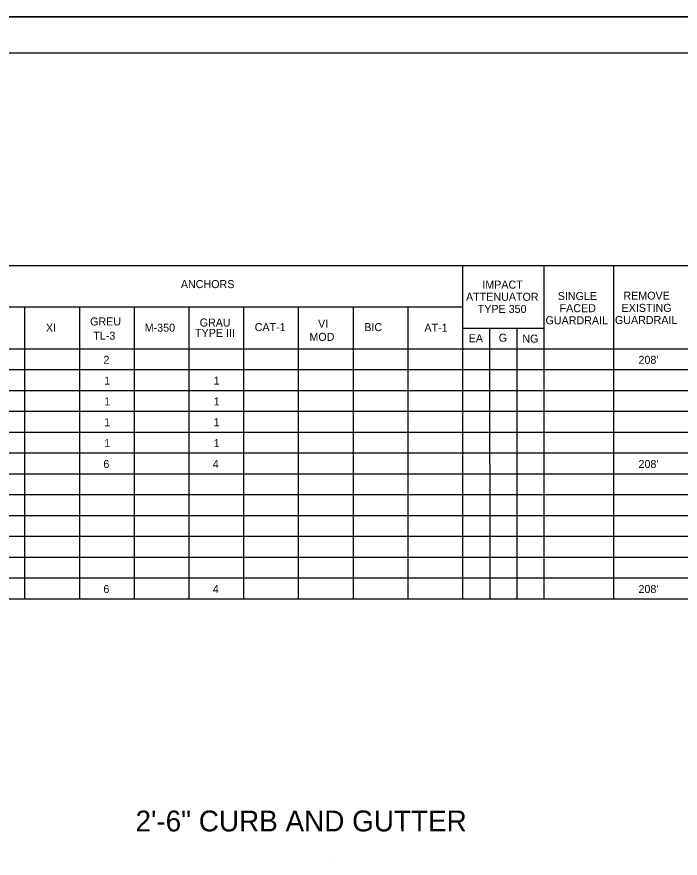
# Model space of a CAD drawing. Extents: x 1184121 to 1184360, y 1246506 to 1246661.
# Drawn here: x 1184248.8 to 1184306.6, y 1246587.1 to 1246660.5 of the extents above; entities that cross this region are included whole.
import ezdxf

# ---------------------------------------------------------------- set-up
doc = ezdxf.new("R2010")
doc.units = 0
for name, color, linetype in [('Sheet Data Field CELL', 7, 'Continuous'), ('Sheet Plan CELL', 7, 'Continuous'), ('Sheet Plot Border Outside CELL', 7, 'Continuous'), ('z - Construction', 7, 'Continuous')]:
    doc.layers.add(name, color=color, linetype=linetype)

msp = doc.modelspace()

# ---------------------------------------------------------------- linework, layer by layer
at = {"layer": 'Sheet Data Field CELL'}
for p, q in [((1184126.184, 1246638.849), (1184344.348, 1246638.849)), ((1184287.618, 1246638.849), (1184287.618, 1246609.761)), ((1184294.723, 1246638.849), (1184294.723, 1246609.761)), ((1184300.802, 1246638.849), (1184300.802, 1246609.761)), ((1184287.618, 1246635.213), (1184218.22, 1246635.213)), ((1184249.439, 1246635.213), (1184249.439, 1246609.761)), ((1184254.21, 1246635.213), (1184254.21, 1246609.761)), ((1184258.987, 1246635.213), (1184258.987, 1246609.761)), ((1184263.758, 1246635.213), (1184263.758, 1246609.761)), ((1184268.528, 1246635.213), (1184268.528, 1246609.761)), ((1184273.299, 1246635.213), (1184273.299, 1246609.761)), ((1184278.077, 1246635.213), (1184278.077, 1246609.761)), ((1184282.847, 1246635.213), (1184282.847, 1246609.761)), ((1184287.618, 1246633.359), (1184294.686, 1246633.359)), ((1184289.981, 1246633.359), (1184289.995, 1246609.761)), ((1184292.359, 1246633.359), (1184292.373, 1246609.761)), ((1184126.184, 1246631.577), (1184344.348, 1246631.577)), ((1184126.184, 1246629.759), (1184344.348, 1246629.759)), ((1184126.184, 1246627.941), (1184344.348, 1246627.941)), ((1184126.184, 1246626.123), (1184344.348, 1246626.123)), ((1184126.184, 1246624.305), (1184344.348, 1246624.305)), ((1184126.184, 1246622.487), (1184344.348, 1246622.487)), ((1184126.184, 1246620.669), (1184344.348, 1246620.669)), ((1184126.184, 1246618.851), (1184344.348, 1246618.851)), ((1184126.184, 1246617.033), (1184344.348, 1246617.033)), ((1184126.184, 1246615.215), (1184344.348, 1246615.215)), ((1184126.184, 1246613.397), (1184344.348, 1246613.397)), ((1184126.184, 1246611.579), (1184344.348, 1246611.579)), ((1184126.184, 1246609.761), (1184344.348, 1246609.761)), ((1184276.549, 1246587.133), (1184276.549, 1246587.133))]:
    msp.add_line(p, q, dxfattribs=at)
at = {"layer": 'Sheet Plan CELL'}
msp.add_line((1184358.423, 1246657.364), (1184126.184, 1246657.364), dxfattribs=at)
at = {"layer": 'Sheet Plot Border Outside CELL'}
msp.add_lwpolyline([(1184121.05, 1246660.53), (1184360.324, 1246660.53), (1184360.324, 1246505.708), (1184121.05, 1246505.708)], close=True, dxfattribs=at)
at = {"layer": 'z - Construction'}
msp.add_line((1184360.324, 1246660.53), (1184121.05, 1246660.53), dxfattribs=at)

# ---------------------------------------------------------------- texts
at = {"layer": 'Sheet Data Field CELL'}
for s, height, p in [('ANCHORS', 0.6981, (1184263.063, 1246636.864)), ('IMPACT', 0.6981, (1184289.355, 1246636.82)), ('ATTENUATOR', 0.6981, (1184287.934, 1246635.758)), ('SINGLE', 0.6981, (1184295.931, 1246635.826)), ('REMOVE', 0.6981, (1184301.659, 1246635.853)), ('TYPE 350', 0.6981, (1184288.953, 1246634.697)), ('FACED', 0.6981, (1184296.094, 1246634.764)), ('EXISTING', 0.6981, (1184301.501, 1246634.791)), ('GREU', 0.6981, (1184255.146, 1246633.606)), ('GRAU', 0.6981, (1184264.703, 1246633.512)), ('GUARDRAIL', 0.6981, (1184294.866, 1246633.702)), ('GUARDRAIL', 0.6981, (1184300.919, 1246633.73)), ('XI', 0.6981, (1184251.295, 1246633.061)), ('M-350', 0.6981, (1184259.91, 1246633.061)), ('CAT-1', 0.6981, (1184269.504, 1246633.111)), ('VI', 0.6981, (1184275.03, 1246633.41)), ('BIC', 0.6981, (1184279.063, 1246633.111)), ('AT-1', 0.6981, (1184284.305, 1246633.053)), ('TL-3', 0.6981, (1184255.426, 1246632.362)), ('TYPE III', 0.6981, (1184264.3, 1246632.609)), ('MOD', 0.6981, (1184274.274, 1246632.261)), ('EA', 0.6981, (1184288.166, 1246632.137)), ('G', 0.698, (1184290.788, 1246632.188)), ('NG', 0.6981, (1184292.847, 1246632.108)), ('2', 0.698, (1184256.309, 1246630.26)), ("208'", 0.6981, (1184302.973, 1246630.26)), ('1', 0.698, (1184256.373, 1246628.442)), ('1', 0.698, (1184265.914, 1246628.442)), ('1', 0.698, (1184256.373, 1246626.624)), ('1', 0.698, (1184265.914, 1246626.624)), ('1', 0.698, (1184256.373, 1246624.806)), ('1', 0.698, (1184265.914, 1246624.806)), ('1', 0.698, (1184256.373, 1246622.988)), ('1', 0.698, (1184265.914, 1246622.988)), ('6', 0.698, (1184256.305, 1246621.17)), ('4', 0.698, (1184265.848, 1246621.17)), ("208'", 0.6981, (1184302.973, 1246621.17)), ('6', 0.698, (1184256.305, 1246610.261)), ('4', 0.698, (1184265.848, 1246610.261)), ("208'", 0.6981, (1184302.973, 1246610.261))]:
    msp.add_text(s, height=height, dxfattribs=at).set_placement(p)
msp.add_text('2\'-6" CURB AND GUTTER', height=1.81805, rotation=0.01193, dxfattribs=at).set_placement((1184259.111, 1246589.462))

doc.saveas('drawing.dxf')
